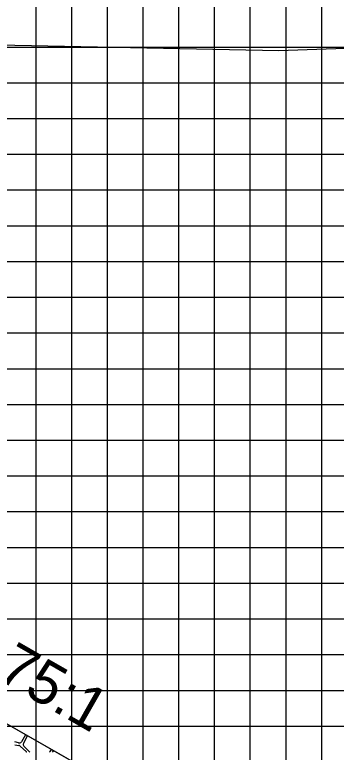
# Model space of a CAD drawing. Extents: x 1769661 to 1770005, y 442591 to 442811.
# Drawn here: x 1769764.41 to 1769773.42, y 442703.93 to 442724.57 of the extents above; entities that cross this region are included whole.
import ezdxf

# ---------------------------------------------------------------- set-up
doc = ezdxf.new("R2010")
doc.units = 0
for name, color, linetype in [('ANNOTATION', 7, 'Continuous'), ('D_Roadway_Centerline', 7, 'Continuous'), ('D_Roadway_SlopeLines', 7, 'Continuous'), ('GRUBBING IN FILL', 7, 'Continuous'), ('MAJOR', 7, 'Continuous'), ('MINOR', 7, 'Continuous'), ('S_Roadway_Centerline', 7, 'Continuous')]:
    doc.layers.add(name, color=color, linetype=linetype)

msp = doc.modelspace()

# ---------------------------------------------------------------- linework, layer by layer
at = {"layer": 'D_Roadway_Centerline'}
msp.add_lwpolyline([(1769729.233, 442723.258), (1769729.933, 442723.212), (1769730.483, 442723.175), (1769731.733, 442722.911), (1769731.746, 442722.907), (1769732.983, 442722.467), (1769734.183, 442721.867), (1769734.233, 442721.842), (1769792.833, 442688.357), (1769792.841, 442688.352), (1769795.425, 442688.998)], dxfattribs=at)
at = {"layer": 'D_Roadway_SlopeLines'}
msp.add_lwpolyline([(1769792.841, 442688.352), (1769734.233, 442721.842), (1769732.983, 442722.467), (1769731.733, 442722.911), (1769730.483, 442723.175), (1769729.233, 442723.258)], dxfattribs=at)
at = {"layer": 'GRUBBING IN FILL'}
for p, q in [((1769764.715, 442704.424), (1769764.6, 442704.227)), ((1769764.523, 442704.195), (1769764.415, 442704.226)), ((1769764.766, 442704.395), (1769764.657, 442704.18)), ((1769764.415, 442704.144), (1769764.531, 442704.124)), ((1769764.566, 442704.107), (1769764.743, 442703.942)), ((1769764.669, 442704.1), (1769764.837, 442703.933)), ((1769765.408, 442703.953), (1769765.448, 442704.005)), ((1769765.386, 442703.933), (1769765.397, 442703.942)), ((1769765.497, 442703.977), (1769765.467, 442703.933))]:
    msp.add_line(p, q, dxfattribs=at)
for centre, major_axis, start_param, end_param in [((1769764.541, 442704.261), (0, -0.0683), 6.004886, 7.327354), ((1769764.519, 442704.057), (0, 0.0683), 5.534807, 6.110994), ((1769764.717, 442704.149), (0, 0.0683), 1.099019, 2.356194), ((1769764.697, 442703.892), (0, 0.0683), 5.35086, 5.534807), ((1769765.354, 442703.995), (0, -0.0683), 0.674741, 0.911486)]:
    msp.add_ellipse(centre, major_axis=major_axis, ratio=0.99895, start_param=start_param, end_param=end_param, dxfattribs=at)
at = {"layer": 'MAJOR'}
for p, q in [((1769767.015, 442678.665), (1769767.015, 442733.665)), ((1769687.015, 442723.665), (1769967.015, 442723.665)), ((1769687.015, 442718.665), (1769967.015, 442718.665)), ((1769687.015, 442713.665), (1769967.015, 442713.665)), ((1769687.015, 442708.665), (1769967.015, 442708.665))]:
    msp.add_line(p, q, dxfattribs=at)
at = {"layer": 'MINOR'}
for p, q in [((1769765.015, 442678.665), (1769765.015, 442733.665)), ((1769766.015, 442678.665), (1769766.015, 442733.665)), ((1769768.015, 442678.665), (1769768.015, 442733.665)), ((1769769.015, 442678.665), (1769769.015, 442733.665)), ((1769770.015, 442678.665), (1769770.015, 442733.665)), ((1769771.015, 442678.665), (1769771.015, 442733.665)), ((1769772.015, 442678.665), (1769772.015, 442733.665)), ((1769773.015, 442678.665), (1769773.015, 442733.665)), ((1769687.015, 442722.665), (1769967.015, 442722.665)), ((1769687.015, 442721.665), (1769967.015, 442721.665)), ((1769687.015, 442720.665), (1769967.015, 442720.665)), ((1769687.015, 442719.665), (1769967.015, 442719.665)), ((1769687.015, 442717.665), (1769967.015, 442717.665)), ((1769687.015, 442716.665), (1769967.015, 442716.665)), ((1769687.015, 442715.665), (1769967.015, 442715.665)), ((1769687.015, 442714.665), (1769967.015, 442714.665)), ((1769687.015, 442712.665), (1769967.015, 442712.665)), ((1769687.015, 442711.665), (1769967.015, 442711.665)), ((1769687.015, 442710.665), (1769967.015, 442710.665)), ((1769687.015, 442709.665), (1769967.015, 442709.665)), ((1769687.015, 442707.665), (1769967.015, 442707.665)), ((1769687.015, 442706.665), (1769967.015, 442706.665)), ((1769687.015, 442705.665), (1769967.015, 442705.665)), ((1769687.015, 442704.665), (1769967.015, 442704.665))]:
    msp.add_line(p, q, dxfattribs=at)
at = {"layer": 'S_Roadway_Centerline'}
msp.add_lwpolyline([(1769719.423, 442723.209), (1769733.43, 442723.28), (1769749.804, 442723.899), (1769751.318, 442723.929), (1769752.067, 442723.947), (1769755.626, 442723.897), (1769771.81, 442723.571), (1769775.271, 442723.69), (1769780.808, 442723.927), (1769791.114, 442724.294), (1769798.336, 442724.276), (1769810.379, 442724.461), (1769811.224, 442724.472), (1769812.696, 442724.389), (1769823.153, 442724.006), (1769829.621, 442723.96), (1769843.106, 442723.704), (1769849.283, 442723.426), (1769858.834, 442723.127)], dxfattribs=at)

# ---------------------------------------------------------------- texts
at = {"layer": 'ANNOTATION'}
msp.add_text('1.75:1', height=1.2, rotation=330.255, dxfattribs=at).set_placement((1769762.702, 442706.678))

doc.saveas('drawing.dxf')
